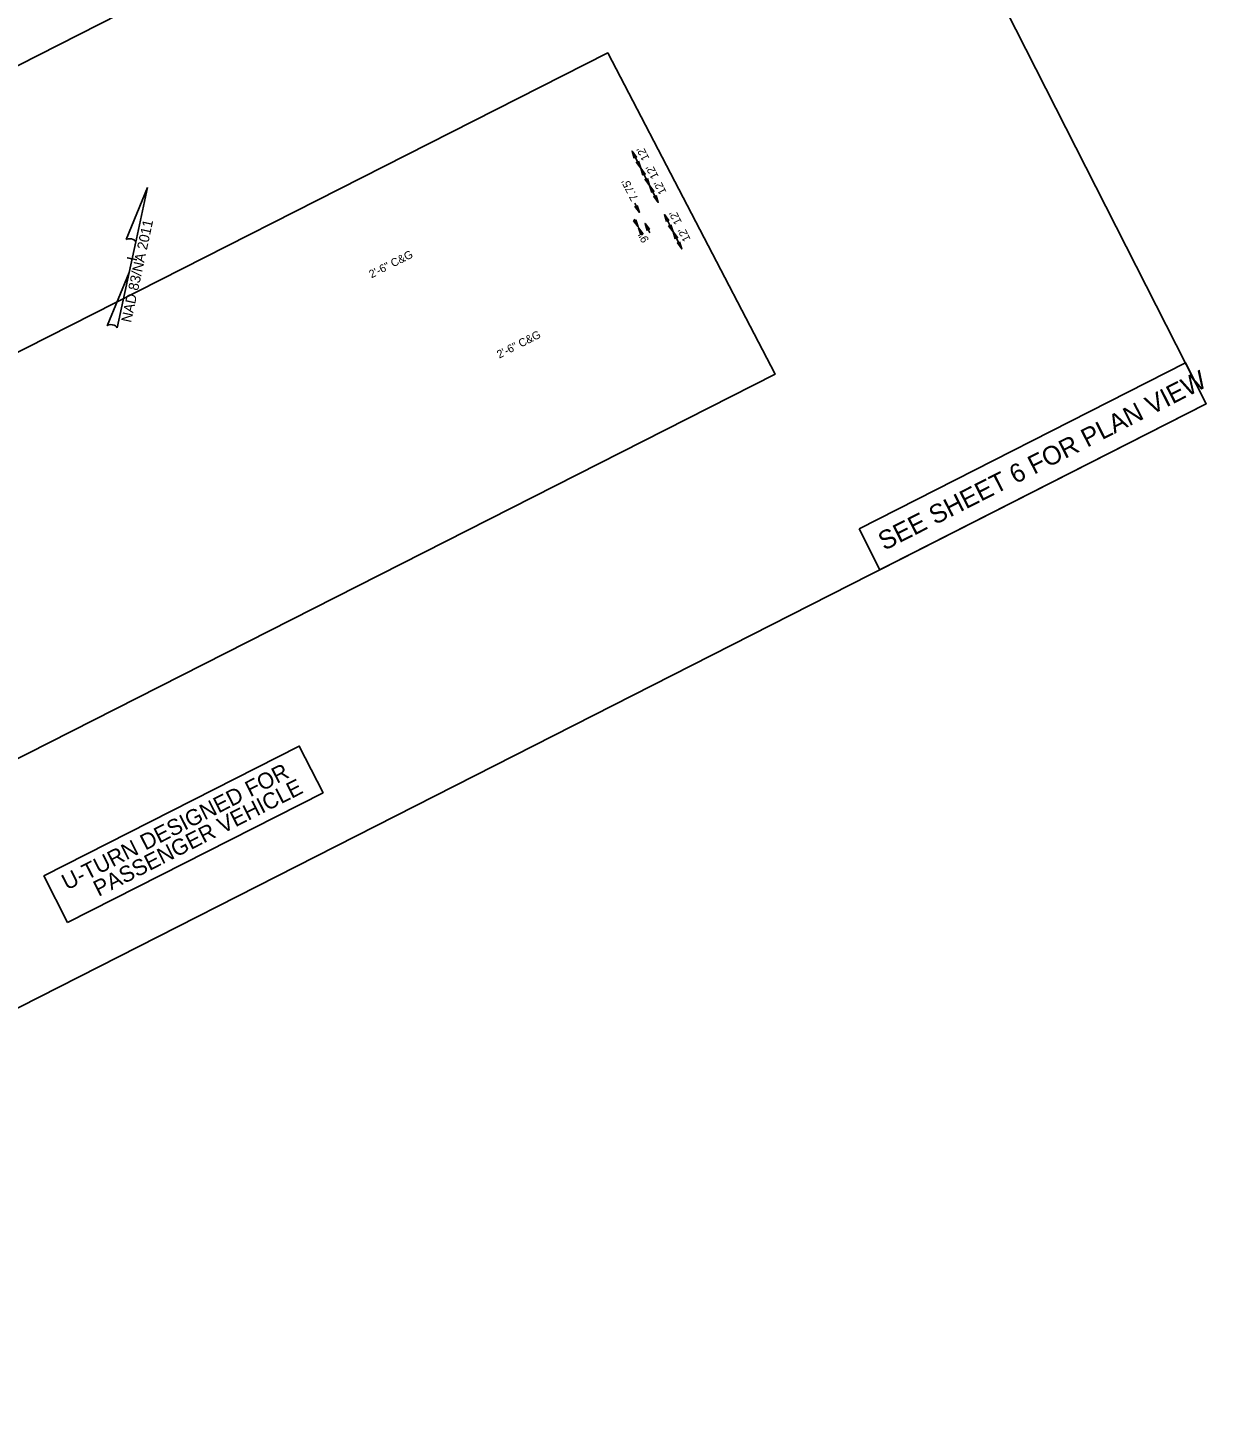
# Model space of a CAD drawing. Extents: x 2331355 to 2333079, y 611262 to 612828.
# Drawn here: x 2332342 to 2333079, y 611262 to 612132 of the extents above; entities that cross this region are included whole.
import ezdxf

# ---------------------------------------------------------------- set-up
doc = ezdxf.new("R2010")
doc.units = 0
for name, color, linetype in [('Default', 7, 'Continuous'), ('Old_Level_2', 7, 'Continuous'), ('Prop North Arrow NAD83 for Plan Sheets CELL', 7, 'Continuous'), ('Scratch_Level_1', 7, 'Continuous'), ('Sheet Plan CELL', 7, 'Continuous')]:
    doc.layers.add(name, color=color, linetype=linetype)

msp = doc.modelspace()

# ---------------------------------------------------------------- linework, layer by layer
at = {"layer": 'Default'}
for points in [[(2332861.83, 611818.55), (2333065.71, 611922.2), (2333078.7, 611896.66), (2332874.82, 611793.01)], [(2332367.25, 611572.48), (2332526.83, 611653.61), (2332511.99, 611682.81), (2332352.4, 611601.68)]]:
    msp.add_lwpolyline(points, close=True, dxfattribs=at)
at = {"layer": 'Old_Level_2'}
for p, q in [((2332725.42, 612043.86), (2332719.97, 612054.56)), ((2332730.86, 612033.17), (2332725.42, 612043.86)), ((2332736.31, 612022.46), (2332730.87, 612033.16)), ((2332721.58, 612022.07), (2332724.53, 612016.28)), ((2332721.3, 612012.02), (2332723.67, 612007.35)), ((2332745.58, 612004.19), (2332740.14, 612014.89)), ((2332724.01, 612006.68), (2332726.39, 612002.01)), ((2332728.04, 612009.37), (2332730.99, 612003.58)), ((2332751.02, 611993.5), (2332745.58, 612004.19))]:
    msp.add_line(p, q, dxfattribs=at)
for points in [[(2332721.32, 612050.2), (2332719.97, 612054.56), (2332722.74, 612050.89), (2332721.76, 612051.04)], [(2332724.07, 612048.23), (2332725.42, 612043.86), (2332722.65, 612047.53), (2332723.62, 612047.38)], [(2332726.77, 612039.5), (2332725.42, 612043.86), (2332728.18, 612040.19), (2332727.21, 612040.34)], [(2332729.51, 612037.53), (2332730.86, 612033.17), (2332728.09, 612036.84), (2332729.07, 612036.69)], [(2332732.22, 612028.79), (2332730.87, 612033.16), (2332733.64, 612029.49), (2332732.66, 612029.64)], [(2332723.18, 612020.64), (2332724.53, 612016.28), (2332721.76, 612019.95), (2332722.74, 612019.8)], [(2332734.96, 612026.82), (2332736.31, 612022.46), (2332733.55, 612026.13), (2332734.52, 612025.98)], [(2332741.49, 612010.53), (2332740.14, 612014.89), (2332742.9, 612011.22), (2332741.93, 612011.37)], [(2332722.32, 612011.71), (2332723.67, 612007.35), (2332720.91, 612011.02), (2332721.88, 612010.87)], [(2332725.36, 612002.32), (2332724.01, 612006.68), (2332726.78, 612003.01), (2332725.81, 612003.16)], [(2332729.4, 612005.01), (2332728.04, 612009.37), (2332730.81, 612005.7), (2332729.84, 612005.85)], [(2332744.23, 612008.56), (2332745.58, 612004.19), (2332742.81, 612007.86), (2332743.79, 612007.71)], [(2332746.93, 611999.83), (2332745.58, 612004.19), (2332748.35, 612000.53), (2332747.37, 612000.67)], [(2332749.67, 611997.86), (2332751.02, 611993.5), (2332748.26, 611997.17), (2332749.23, 611997.02)]]:
    msp.add_lwpolyline(points, close=True, dxfattribs=at)
at = {"layer": 'Prop North Arrow NAD83 for Plan Sheets CELL'}
for p, q in [((2332403.8, 611999.26), (2332417.19, 612031.93)), ((2332417.22, 612031.92), (2332409.62, 611996.88)), ((2332417.22, 612031.92), (2332417.19, 612031.93)), ((2332417.22, 612031.92), (2332417.19, 612031.93)), ((2332405.67, 611978.71), (2332409.84, 611997.91)), ((2332409.62, 611996.88), (2332409.83, 611997.87)), ((2332404.58, 611987.85), (2332404.55, 611987.85)), ((2332407.19, 611987.28), (2332404.58, 611987.85)), ((2332404.62, 611987.84), (2332410.48, 611986.57)), ((2332405.67, 611978.71), (2332392.03, 611945.41)), ((2332398.22, 611944.22), (2332405.67, 611978.71))]:
    msp.add_line(p, q, dxfattribs=at)
for centre, start_param, end_param in [((2332406.75, 611998.24), 0.216388, 2.908219), ((2332395.11, 611944.61), 0.201328, 3.141593)]:
    msp.add_ellipse(centre, major_axis=(3.1, -0.7), ratio=0.461098, start_param=start_param, end_param=end_param, dxfattribs=at)
at = {"layer": 'Scratch_Level_1'}
msp.add_lwpolyline([(2331837.64, 611676.12), (2332704.77, 612115.95), (2332809.39, 611915.29), (2331984.65, 611496.71), (2331946.94, 611570.91), (2331905.9, 611550.04), (2331846.41, 611665.97)], close=True, dxfattribs=at)
at = {"layer": 'Sheet Plan CELL'}
for points in [[(2331354.84, 612198.14), (2332231.99, 612644.09), (2332248.84, 612610.95), (2332379.58, 612677.42), (2332421.89, 612594.18), (2332493.28, 612630.48), (2332529.96, 612558.33), (2332698.67, 612644.11), (2332840.79, 612364.62), (2331592.76, 611730.15)], [(2331592.76, 611730.15), (2332840.78, 612364.62), (2333078.69, 611896.65), (2331830.66, 611262.19)]]:
    msp.add_lwpolyline(points, close=True, dxfattribs=at)

# ---------------------------------------------------------------- texts
at = {"layer": 'Default'}
for s, height, rotation, p in [('SEE SHEET 6 FOR PLAN VIEW', 11.6664, 26.94752, (2332877.56, 611804.74)), ('U-TURN DESIGNED FOR ', 10, 26.94767, (2332366.83, 611592.49)), ('PASSENGER VEHICLE', 10, 26.94767, (2332386.6, 611588.51))]:
    msp.add_text(s, height=height, rotation=rotation, dxfattribs=at).set_placement(p)
at = {"layer": 'Old_Level_2'}
for s, rotation, p in [("12'", 116.97858, (2332730.88, 612050.12)), ("12'", 116.97858, (2332736.69, 612038.71)), ("7.75'", 116.97858, (2332723.98, 612025.02)), ("12'", 116.97858, (2332741.64, 612028.98)), ("12'", 116.97858, (2332751.21, 612010.18)), ("12'", 116.97858, (2332756.66, 611999.48)), ('9"', 116.97858, (2332730.72, 611998.94)), ('2\'-6" C&G', 26.97858, (2332557.13, 611975.01)), ('2\'-6" C&G', 26.97858, (2332637, 611924.9))]:
    msp.add_text(s, height=5, rotation=rotation, dxfattribs=at).set_placement(p)
at = {"layer": 'Prop North Arrow NAD83 for Plan Sheets CELL'}
msp.add_text('NAD 83/NA 2011', height=6.375, rotation=77.75059, dxfattribs=at).set_placement((2332406.88, 611947.11))

doc.saveas('drawing.dxf')
